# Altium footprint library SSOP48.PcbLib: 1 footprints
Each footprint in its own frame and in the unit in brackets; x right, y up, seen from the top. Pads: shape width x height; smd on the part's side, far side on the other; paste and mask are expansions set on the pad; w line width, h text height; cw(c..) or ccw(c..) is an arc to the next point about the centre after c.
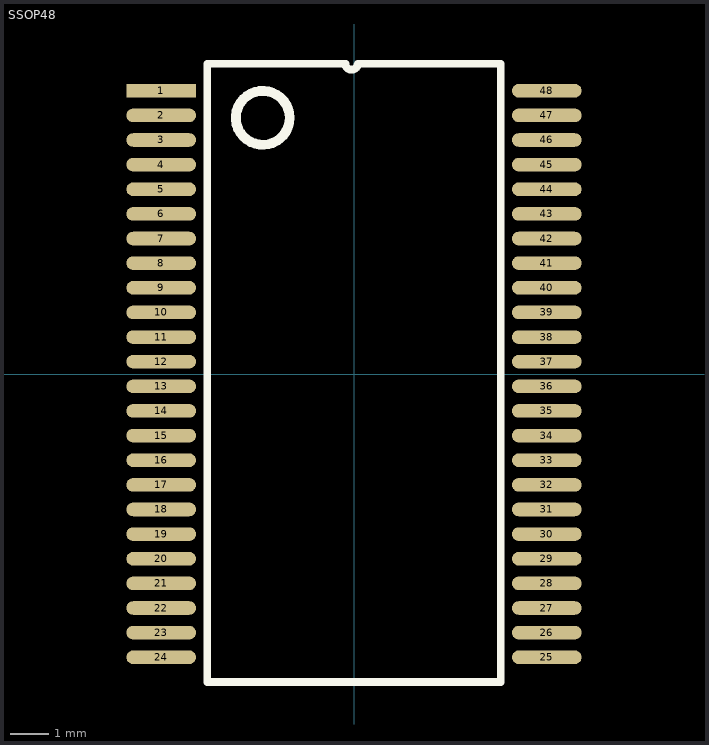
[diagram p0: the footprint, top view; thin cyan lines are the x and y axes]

## SSOP48 [mm]
pads (48):
  rect 1.8x0.35 smd: 1(-4.97,7.302)
  oval 1.8x0.35 smd: 2(-4.97,6.667) 3(-4.97,6.032) 4(-4.97,5.397) 5(-4.97,4.763) 6(-4.97,4.127) 7(-4.97,3.492) 8(-4.97,2.857) 9(-4.97,2.222) 10(-4.97,1.587) 11(-4.97,0.953) 12(-4.97,0.318) 13(-4.97,-0.318) 14(-4.97,-0.953) 15(-4.97,-1.587) 16(-4.97,-2.222) 17(-4.97,-2.857) 18(-4.97,-3.492) 19(-4.97,-4.127) 20(-4.97,-4.763) 21(-4.97,-5.397) 22(-4.97,-6.032) 23(-4.97,-6.667) 24(-4.97,-7.302) 25(4.97,-7.302) 26(4.97,-6.667) 27(4.97,-6.032) 28(4.97,-5.397) 29(4.97,-4.763) 30(4.97,-4.127) 31(4.97,-3.492) 32(4.97,-2.857) 33(4.97,-2.222) 34(4.97,-1.587) 35(4.97,-0.953) 36(4.97,-0.318) 37(4.97,0.318) 38(4.97,0.953) 39(4.97,1.587) 40(4.97,2.222) 41(4.97,2.857) 42(4.97,3.492) 43(4.97,4.127) 44(4.97,4.763) 45(4.97,5.397) 46(4.97,6.032) 47(4.97,6.667) 48(4.97,7.302)
Top Overlay:
  circle w0.254: c-2.353,6.604 r0.695
  lines w0.2: -3.78,-7.937 3.78,-7.937 3.78,8.001 0.095,8.001 cw(c-0.064,8.001) -0.222,8.001 -3.78,8.001 -3.78,-7.938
